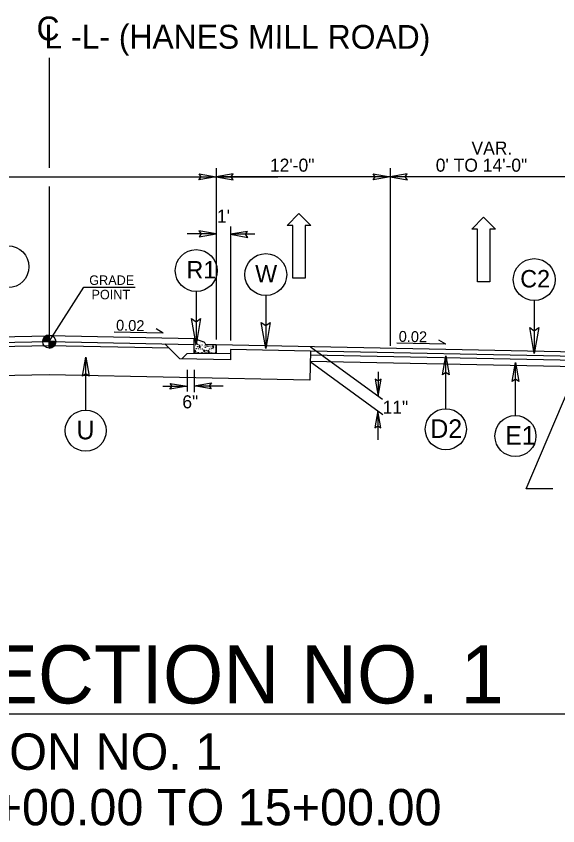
# Model space of a CAD drawing. Extents: x 1904401 to 1905163, y 193929 to 194736.
# Drawn here: x 1904578.2 to 1904615.5, y 194572.5 to 194628.2 of the extents above; entities that cross this region are included whole.
import ezdxf

# ---------------------------------------------------------------- set-up
doc = ezdxf.new("R2010")
doc.units = 0
for name, color, linetype in [('Default', 7, 'Continuous'), ('Old_Level_11', 7, 'Continuous'), ('Old_Level_20', 7, 'Continuous'), ('Prop Lane Arrow CELL', 7, 'Continuous'), ('Typical Arrow Superelevation CELL', 7, 'Continuous'), ('Typical Berm CELL', 7, 'Continuous'), ('Typical Curb CELL', 7, 'Continuous'), ('Typical Grade Point Symbol CELL', 7, 'Continuous'), ('Typical ID Circle CELL', 7, 'Continuous'), ('Typical Pavement Slope CELL', 7, 'Continuous'), ('Typical Terminator CELL', 7, 'Continuous'), ('Typical Text Centerline CELL', 7, 'Continuous'), ('Typical Text Grade Point CELL', 7, 'Continuous'), ('Typical Text ID Circle CELL', 7, 'Continuous')]:
    doc.layers.add(name, color=color, linetype=linetype)

msp = doc.modelspace()

# ---------------------------------------------------------------- linework, layer by layer
at = {"layer": 'Default'}
for p, q in [((1904591.938, 194617.771), (1904591.938, 194605.974)), ((1904592.938, 194613.745), (1904592.938, 194605.898))]:
    msp.add_line(p, q, dxfattribs=at)
at = {"layer": 'Old_Level_11'}
for p, q in [((1904582.954, 194601.105), (1904582.954, 194604.759)), ((1904607.767, 194601.202), (1904607.767, 194604.856)), ((1904612.563, 194600.733), (1904612.563, 194604.387))]:
    msp.add_line(p, q, dxfattribs=at)
for points in [[(1904582.729, 194603.45), (1904582.954, 194604.759), (1904583.187, 194603.443), (1904582.954, 194603.61)], [(1904607.542, 194603.547), (1904607.767, 194604.856), (1904608, 194603.54), (1904607.767, 194603.707)], [(1904612.338, 194603.078), (1904612.563, 194604.387), (1904612.796, 194603.071), (1904612.563, 194603.238)]]:
    msp.add_lwpolyline(points, close=True, dxfattribs=at)
for centre in [(1904607.767, 194599.788), (1904582.954, 194599.69), (1904612.563, 194599.319)]:
    msp.add_circle(centre, 1.414, dxfattribs=at)
at = {"layer": 'Prop Lane Arrow CELL'}
for p, q in [((1904557.188, 194617.188), (1904591.938, 194617.188)), ((1904603.938, 194617.188), (1904591.938, 194617.188)), ((1904603.188, 194617.188), (1904592.188, 194617.188)), ((1904592.188, 194617.188), (1904596.188, 194617.188)), ((1904617.938, 194617.188), (1904603.938, 194617.188)), ((1904596.836, 194613.83), (1904597.64, 194614.647)), ((1904597.64, 194614.647), (1904598.47, 194613.83)), ((1904597.225, 194613.83), (1904596.836, 194613.83)), ((1904597.225, 194610.199), (1904597.225, 194613.83)), ((1904598.47, 194613.83), (1904598.081, 194613.83)), ((1904598.081, 194613.83), (1904598.081, 194610.199)), ((1904591.938, 194613.244), (1904589.947, 194613.244)), ((1904594.609, 194613.216), (1904592.938, 194613.216)), ((1904598.081, 194610.199), (1904597.225, 194610.199)), ((1904598.451, 194605.466), (1904603.393, 194601.856)), ((1904598.423, 194604.46), (1904603.42, 194600.81)), ((1904613.308, 194595.673), (1904616.872, 194604.091)), ((1904589.938, 194603.891), (1904589.938, 194602.393)), ((1904590.438, 194603.891), (1904590.438, 194602.353)), ((1904603.107, 194603.736), (1904603.107, 194602.064)), ((1904588.266, 194602.747), (1904589.938, 194602.747)), ((1904590.438, 194602.774), (1904592.428, 194602.774)), ((1904603.079, 194601.058), (1904603.079, 194599.068)), ((1904615.129, 194595.673), (1904613.308, 194595.673)), ((1904540.042, 194580.172), (1904621.321, 194580.172))]:
    msp.add_line(p, q, dxfattribs=at)
at = {"layer": 'Typical Arrow Superelevation CELL'}
for p, q in [((1904588.29, 194606.413), (1904584.916, 194606.48)), ((1904588.29, 194606.413), (1904587.82, 194606.697)), ((1904607.764, 194605.644), (1904604.39, 194605.712)), ((1904607.764, 194605.644), (1904607.295, 194605.928))]:
    msp.add_line(p, q, dxfattribs=at)
at = {"layer": 'Typical Berm CELL'}
for p, q in [((1904603.938, 194617.771), (1904603.938, 194605.534)), ((1904609.55, 194613.583), (1904610.354, 194614.4)), ((1904610.354, 194614.4), (1904611.184, 194613.583)), ((1904609.939, 194613.583), (1904609.55, 194613.583)), ((1904609.939, 194609.952), (1904609.939, 194613.583)), ((1904611.184, 194613.583), (1904610.795, 194613.583)), ((1904610.795, 194613.583), (1904610.795, 194609.952)), ((1904610.795, 194609.952), (1904609.939, 194609.952)), ((1904580.438, 194605.537), (1904562.438, 194605.177)), ((1904588.71, 194605.37), (1904580.438, 194605.537)), ((1904598.438, 194605.175), (1904592.938, 194605.285)), ((1904598.438, 194605.175), (1904598.398, 194603.175)), ((1904580.438, 194603.536), (1904562.478, 194603.177)), ((1904598.398, 194603.175), (1904580.438, 194603.536))]:
    msp.add_line(p, q, dxfattribs=at)
at = {"layer": 'Typical Curb CELL'}
for p, q in [((1904590.438, 194605.013), (1904590.438, 194606.013)), ((1904591.124, 194605.784), (1904590.438, 194606.013)), ((1904590.585, 194605.841), (1904590.499, 194605.841)), ((1904590.499, 194605.841), (1904590.58, 194605.755)), ((1904590.58, 194605.755), (1904590.585, 194605.841)), ((1904591.188, 194605.69), (1904591.188, 194605.696)), ((1904590.526, 194605.223), (1904590.453, 194605.209)), ((1904590.453, 194605.209), (1904590.49, 194605.1)), ((1904590.49, 194605.1), (1904590.526, 194605.223)), ((1904590.783, 194605.539), (1904590.825, 194605.389)), ((1904590.865, 194605.48), (1904590.783, 194605.539)), ((1904590.825, 194605.389), (1904590.865, 194605.48)), ((1904591.091, 194605.25), (1904591.181, 194605.2)), ((1904591.122, 194605.119), (1904591.091, 194605.25)), ((1904591.181, 194605.2), (1904591.122, 194605.119)), ((1904591.938, 194605.596), (1904591.281, 194605.596)), ((1904591.445, 194605.207), (1904591.373, 194605.193)), ((1904591.373, 194605.193), (1904591.409, 194605.084)), ((1904591.409, 194605.084), (1904591.445, 194605.207)), ((1904591.702, 194605.523), (1904591.744, 194605.374)), ((1904591.784, 194605.464), (1904591.702, 194605.523)), ((1904591.744, 194605.374), (1904591.784, 194605.464)), ((1904591.938, 194605.596), (1904591.938, 194605.013)), ((1904591.938, 194605.013), (1904591.938, 194605.59)), ((1904591.938, 194605.013), (1904590.438, 194605.013))]:
    msp.add_line(p, q, dxfattribs=at)
for centre in [(1904590.648, 194605.927), (1904590.675, 194605.643), (1904590.865, 194605.737), (1904591, 194605.76), (1904590.513, 194605.602), (1904590.521, 194605.493), (1904590.558, 194605.123), (1904590.58, 194605.335), (1904590.671, 194605.48), (1904590.702, 194605.082), (1904590.716, 194605.349), (1904590.729, 194605.254), (1904590.793, 194605.593), (1904590.865, 194605.317), (1904590.96, 194605.462), (1904590.978, 194605.186), (1904590.982, 194605.597), (1904591.009, 194605.322), (1904591.05, 194605.507), (1904591.172, 194605.534), (1904591.195, 194605.435), (1904591.285, 194605.2), (1904591.301, 194605.279), (1904591.308, 194605.512), (1904591.323, 194605.482), (1904591.441, 194605.478), (1904591.477, 194605.107), (1904591.499, 194605.32), (1904591.59, 194605.464), (1904591.635, 194605.333), (1904591.648, 194605.238), (1904591.712, 194605.577), (1904591.784, 194605.302), (1904591.879, 194605.446), (1904591.897, 194605.171), (1904591.929, 194605.306), (1904590.964, 194605.064), (1904591.208, 194605.06), (1904591.285, 194605.046), (1904591.621, 194605.067), (1904591.883, 194605.049)]:
    msp.add_circle(centre, 0.00635, dxfattribs=at)
for centre, radius, start, end in [((1904591.094, 194605.696), 0.0937, 0, 71.5651), ((1904591.281, 194605.69), 0.0937, 180, 270), ((1904590.472, 194605.019), 0.00635, 27.0386, 154.2416)]:
    msp.add_arc(centre, radius, start, end, dxfattribs=at)
at = {"layer": 'Typical Grade Point Symbol CELL'}
for p, q in [((1904580.438, 194605.826), (1904580.438, 194606.274)), ((1904579.99, 194605.826), (1904580.438, 194605.826)), ((1904580.439, 194605.379), (1904580.438, 194605.826)), ((1904580.885, 194605.826), (1904580.438, 194605.826)), ((1904580.438, 194605.826), (1904580.439, 194605.379))]:
    msp.add_line(p, q, dxfattribs=at)
for points in [[(1904580.192, 194606.2), (1904580.192, 194605.826)], [(1904580.201, 194606.206), (1904580.201, 194605.826)], [(1904580.21, 194606.211), (1904580.21, 194605.826)], [(1904580.219, 194606.216), (1904580.219, 194605.826)], [(1904580.228, 194606.221), (1904580.228, 194605.826)], [(1904580.237, 194606.226), (1904580.237, 194605.826)], [(1904580.246, 194606.23), (1904580.246, 194605.826)], [(1904580.255, 194606.234), (1904580.255, 194605.826)], [(1904580.264, 194606.238), (1904580.264, 194605.826)], [(1904580.272, 194606.242), (1904580.272, 194605.826)], [(1904580.281, 194606.246), (1904580.281, 194605.826)], [(1904580.29, 194606.249), (1904580.29, 194605.826)], [(1904580.299, 194606.252), (1904580.299, 194605.826)], [(1904580.308, 194606.255), (1904580.308, 194605.826)], [(1904580.317, 194606.257), (1904580.317, 194605.826)], [(1904580.326, 194606.26), (1904580.326, 194605.826)], [(1904580.335, 194606.262), (1904580.335, 194605.826)], [(1904580.344, 194606.264), (1904580.344, 194605.826)], [(1904580.353, 194606.266), (1904580.353, 194605.826)], [(1904580.362, 194606.268), (1904580.362, 194605.826)], [(1904580.371, 194606.269), (1904580.371, 194605.826)], [(1904580.38, 194606.27), (1904580.38, 194605.826)], [(1904580.389, 194606.271), (1904580.389, 194605.826)], [(1904580.398, 194606.272), (1904580.398, 194605.826)], [(1904580.407, 194606.273), (1904580.407, 194605.826)], [(1904580.416, 194606.273), (1904580.416, 194605.826)], [(1904580.425, 194606.274), (1904580.425, 194605.826)], [(1904580.434, 194606.274), (1904580.434, 194606.274), (1904580.434, 194605.826)], [(1904579.995, 194605.89), (1904579.995, 194605.826)], [(1904580.004, 194605.936), (1904580.004, 194605.826)], [(1904580.013, 194605.967), (1904580.013, 194605.826)], [(1904580.022, 194605.992), (1904580.022, 194605.826)], [(1904580.031, 194606.012), (1904580.031, 194605.826)], [(1904580.04, 194606.031), (1904580.04, 194605.826)], [(1904580.049, 194606.047), (1904580.049, 194605.826)], [(1904580.058, 194606.062), (1904580.058, 194605.826)], [(1904580.067, 194606.076), (1904580.067, 194605.826)], [(1904580.076, 194606.089), (1904580.076, 194605.826)], [(1904580.084, 194606.101), (1904580.084, 194605.826)], [(1904580.093, 194606.112), (1904580.093, 194605.826)], [(1904580.102, 194606.123), (1904580.102, 194605.826)], [(1904580.111, 194606.133), (1904580.111, 194605.826)], [(1904580.12, 194606.142), (1904580.12, 194605.826)], [(1904580.129, 194606.151), (1904580.129, 194605.826)], [(1904580.138, 194606.159), (1904580.138, 194605.826)], [(1904580.147, 194606.167), (1904580.147, 194605.826)], [(1904580.156, 194606.175), (1904580.156, 194605.826)], [(1904580.165, 194606.181), (1904580.165, 194605.826)], [(1904580.174, 194606.187), (1904580.174, 194605.826)], [(1904580.183, 194606.194), (1904580.183, 194605.826)], [(1904580.445, 194605.826), (1904580.445, 194605.379), (1904580.445, 194605.379)], [(1904580.453, 194605.826), (1904580.453, 194605.379)], [(1904580.462, 194605.826), (1904580.462, 194605.38)], [(1904580.471, 194605.826), (1904580.471, 194605.38)], [(1904580.48, 194605.826), (1904580.48, 194605.381)], [(1904580.489, 194605.826), (1904580.489, 194605.382)], [(1904580.498, 194605.826), (1904580.498, 194605.383)], [(1904580.507, 194605.826), (1904580.507, 194605.385)], [(1904580.516, 194605.826), (1904580.516, 194605.386)], [(1904580.525, 194605.826), (1904580.525, 194605.388)], [(1904580.534, 194605.826), (1904580.534, 194605.39)], [(1904580.543, 194605.826), (1904580.543, 194605.392)], [(1904580.552, 194605.826), (1904580.552, 194605.394)], [(1904580.561, 194605.826), (1904580.561, 194605.397)], [(1904580.57, 194605.826), (1904580.57, 194605.399)], [(1904580.579, 194605.826), (1904580.579, 194605.402)], [(1904580.588, 194605.826), (1904580.588, 194605.405)], [(1904580.597, 194605.826), (1904580.597, 194605.408)], [(1904580.606, 194605.826), (1904580.606, 194605.412)], [(1904580.615, 194605.826), (1904580.615, 194605.416)], [(1904580.624, 194605.826), (1904580.624, 194605.42)], [(1904580.633, 194605.826), (1904580.633, 194605.424)], [(1904580.641, 194605.826), (1904580.641, 194605.428)], [(1904580.65, 194605.826), (1904580.65, 194605.433)], [(1904580.659, 194605.826), (1904580.659, 194605.437)], [(1904580.668, 194605.826), (1904580.668, 194605.442)], [(1904580.677, 194605.826), (1904580.677, 194605.448)], [(1904580.686, 194605.826), (1904580.686, 194605.454)], [(1904580.695, 194605.826), (1904580.695, 194605.46)], [(1904580.704, 194605.826), (1904580.704, 194605.466)], [(1904580.713, 194605.826), (1904580.713, 194605.473)], [(1904580.722, 194605.826), (1904580.722, 194605.48)], [(1904580.731, 194605.826), (1904580.731, 194605.488)], [(1904580.74, 194605.826), (1904580.74, 194605.496)], [(1904580.749, 194605.826), (1904580.749, 194605.504)], [(1904580.758, 194605.826), (1904580.758, 194605.513)], [(1904580.767, 194605.826), (1904580.767, 194605.523)], [(1904580.776, 194605.826), (1904580.776, 194605.533)], [(1904580.785, 194605.826), (1904580.785, 194605.544)], [(1904580.794, 194605.826), (1904580.794, 194605.555)], [(1904580.803, 194605.826), (1904580.803, 194605.567)], [(1904580.812, 194605.826), (1904580.812, 194605.58)], [(1904580.821, 194605.826), (1904580.821, 194605.594)], [(1904580.829, 194605.826), (1904580.829, 194605.61)], [(1904580.838, 194605.826), (1904580.838, 194605.626)], [(1904580.847, 194605.826), (1904580.847, 194605.645)], [(1904580.856, 194605.826), (1904580.856, 194605.666)], [(1904580.865, 194605.826), (1904580.865, 194605.693)], [(1904580.874, 194605.826), (1904580.874, 194605.725)], [(1904580.883, 194605.826), (1904580.883, 194605.778)]]:
    msp.add_lwpolyline(points, dxfattribs=at)
msp.add_circle((1904580.438, 194605.827), 0.448, dxfattribs=at)
for start, end in [(90.0095, 180.0095), (270.0095, 0.0095)]:
    msp.add_arc((1904580.438, 194605.827), 0.448, start, end, dxfattribs=at)
at = {"layer": 'Typical ID Circle CELL'}
for p, q in [((1904590.568, 194609.275), (1904590.568, 194605.635)), ((1904595.362, 194609.001), (1904595.362, 194605.36)), ((1904613.86, 194608.655), (1904613.86, 194605.015))]:
    msp.add_line(p, q, dxfattribs=at)
for centre in [(1904577.603, 194610.985), (1904590.568, 194610.718), (1904595.362, 194610.443), (1904613.86, 194610.098)]:
    msp.add_circle(centre, 1.443, dxfattribs=at)
at = {"layer": 'Typical Pavement Slope CELL'}
for p, q in [((1904558.673, 194605.778), (1904580.438, 194606.219)), ((1904590.438, 194606.013), (1904580.438, 194606.219)), ((1904558.673, 194605.391), (1904580.438, 194605.826)), ((1904580.438, 194605.826), (1904590.438, 194605.626)), ((1904589.438, 194604.642), (1904588.413, 194605.667)), ((1904617.938, 194605.076), (1904591.938, 194605.596)), ((1904592.938, 194605.285), (1904592.938, 194604.573)), ((1904617.938, 194604.785), (1904598.438, 194605.175)), ((1904592.938, 194604.573), (1904589.438, 194604.642)), ((1904589.567, 194604.632), (1904589.938, 194605.003)), ((1904589.938, 194605.003), (1904592.938, 194605.031)), ((1904617.938, 194604.493), (1904598.432, 194604.883)), ((1904621.42, 194604), (1904598.423, 194604.46))]:
    msp.add_line(p, q, dxfattribs=at)
at = {"layer": 'Typical Terminator CELL'}
for points in [[(1904590.766, 194617.389), (1904591.938, 194617.188), (1904590.759, 194616.979), (1904590.909, 194617.188)], [(1904593.109, 194617.389), (1904591.938, 194617.188), (1904593.116, 194616.979), (1904592.966, 194617.188)], [(1904602.766, 194617.389), (1904603.938, 194617.188), (1904602.759, 194616.979), (1904602.909, 194617.188)], [(1904605.109, 194617.389), (1904603.938, 194617.188), (1904605.116, 194616.979), (1904604.966, 194617.188)], [(1904590.766, 194613.042), (1904591.938, 194613.244), (1904590.759, 194613.452), (1904590.909, 194613.244)], [(1904594.109, 194613.418), (1904592.938, 194613.216), (1904594.116, 194613.008), (1904593.966, 194613.216)], [(1904590.874, 194607.416), (1904590.568, 194605.635), (1904590.251, 194607.425), (1904590.568, 194607.198)], [(1904595.669, 194607.141), (1904595.362, 194605.36), (1904595.045, 194607.151), (1904595.362, 194606.924)], [(1904614.166, 194606.796), (1904613.86, 194605.015), (1904613.543, 194606.805), (1904613.86, 194606.578)], [(1904588.766, 194602.949), (1904589.938, 194602.747), (1904588.76, 194602.539), (1904588.91, 194602.747)], [(1904591.61, 194602.573), (1904590.438, 194602.774), (1904591.616, 194602.983), (1904591.466, 194602.774)], [(1904602.905, 194603.236), (1904603.107, 194602.064), (1904603.315, 194603.243), (1904603.107, 194603.093)], [(1904603.281, 194599.887), (1904603.079, 194601.058), (1904602.871, 194599.88), (1904603.079, 194600.03)]]:
    msp.add_lwpolyline(points, close=True, dxfattribs=at)
at = {"layer": 'Typical Text Centerline CELL'}
for p, q in [((1904580.438, 194625.372), (1904580.438, 194621.715)), ((1904580.438, 194621.715), (1904580.438, 194617.789)), ((1904580.438, 194616.516), (1904580.438, 194605.826))]:
    msp.add_line(p, q, dxfattribs=at)
at = {"layer": 'Typical Text Grade Point CELL'}
for p, q in [((1904580.438, 194605.826), (1904582.833, 194609.575)), ((1904582.833, 194609.575), (1904586.371, 194609.575))]:
    msp.add_line(p, q, dxfattribs=at)

# ---------------------------------------------------------------- texts
at = {"layer": 'Old_Level_20'}
for s, height, p in [('U', 1.279, (1904582.321, 194599.093)), ('D2', 1.2792, (1904606.702, 194599.19)), ('E1', 1.2792, (1904611.855, 194598.721))]:
    msp.add_text(s, height=height, dxfattribs=at).set_placement(p)
at = {"layer": 'Prop Lane Arrow CELL'}
for s, height, p in [('VAR.', 0.9, (1904609.535, 194618.711)), ('12\'-0"', 0.9, (1904595.648, 194617.531)), ('0\' TO 14\'-0"', 0.9, (1904607.072, 194617.531)), ('TYPICAL SECTION NO. 1', 4, (1904548.743, 194580.898)), ('USE TYPICAL SECTION NO. 1', 2.5, (1904545.178, 194576.327)), ('-L- STA. 12+00.00 TO 15+00.00', 2.5, (1904559.52, 194572.502))]:
    msp.add_text(s, height=height, dxfattribs=at).set_placement(p)
for s, height, rotation, p in [("1'", 0.9, 0.0002, (1904591.995, 194614.012)), ('0.02', 0.7499, 358.8538, (1904585.041, 194606.583)), ('0.02', 0.7499, 358.8538, (1904604.515, 194605.814)), ('6"', 0.9, 359.9998, (1904589.612, 194601.227)), ('11"', 0.9, 0.0002, (1904603.409, 194600.852))]:
    msp.add_text(s, height=height, rotation=rotation, dxfattribs=at).set_placement(p)
at = {"layer": 'Typical Text Centerline CELL'}
msp.add_text('C', height=1.64, dxfattribs=at).set_placement((1904579.569, 194626.58))
msp.add_text('L -L- (HANES MILL ROAD)', height=1.64109, rotation=359.9469, dxfattribs=at).set_placement((1904580.115, 194626.02))
at = {"layer": 'Typical Text Grade Point CELL'}
for s, p in [('GRADE', (1904583.197, 194609.731)), ('POINT', (1904583.354, 194608.742))]:
    msp.add_text(s, height=0.6525, dxfattribs=at).set_placement(p)
at = {"layer": 'Typical Text ID Circle CELL'}
for s, p in [('R1', (1904589.897, 194610.177)), ('W', (1904594.631, 194609.903)), ('C2', (1904612.894, 194609.557))]:
    msp.add_text(s, height=1.2, rotation=360, dxfattribs=at).set_placement(p)

doc.saveas('drawing.dxf')
